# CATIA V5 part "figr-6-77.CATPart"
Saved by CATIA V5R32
Part number: Part1
Bounding box of the stored display mesh (mm): x -73.764 to 84.089, y -55.398 to 52.667, z 0 to 30
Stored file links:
  D:\PROJECTS\Project 2022\CATIA V5 6R 2022\Resources\Part Files\c06_catia_v5_6r2022_prt\figr-6-77.CATPart
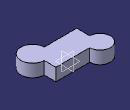
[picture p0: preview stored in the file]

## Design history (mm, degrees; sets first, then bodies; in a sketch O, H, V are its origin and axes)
Body1 (main body)
  Sketch1 on xy-plane, origin (0, 0, 0), H (1, 0, 0), V (0, 1, 0)
    arc A1 centre (-49.155, 28.0584) radius 24.6929 from (-24.4621, 28.0584) to (-49.155, 3.3655) ccw
    line L1 (-24.4621, 28.0584) -> (56.3278, 28.0584)
    line L2 (56.3278, 28.0584) -> (56.3278, 0.211)
    line L3 (28.4803, -27.6365) -> (-49.155, -27.6365)
    line L4 (-49.155, -27.6365) -> (-49.155, 3.3655)
    arc A2 centre (56.3278, -27.6365) radius 27.8474 from (28.4803, -27.6365) to (56.3278, 0.211) ccw
    point P5 (56.3278, 0.211)
    horizontal: L1 H, L3 H
    vertical: L2 V, L4 V
    coincidence: A2 P5, L2 P5
  Pad1: profile Sketch1, direction (0, 0, 1), length 30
